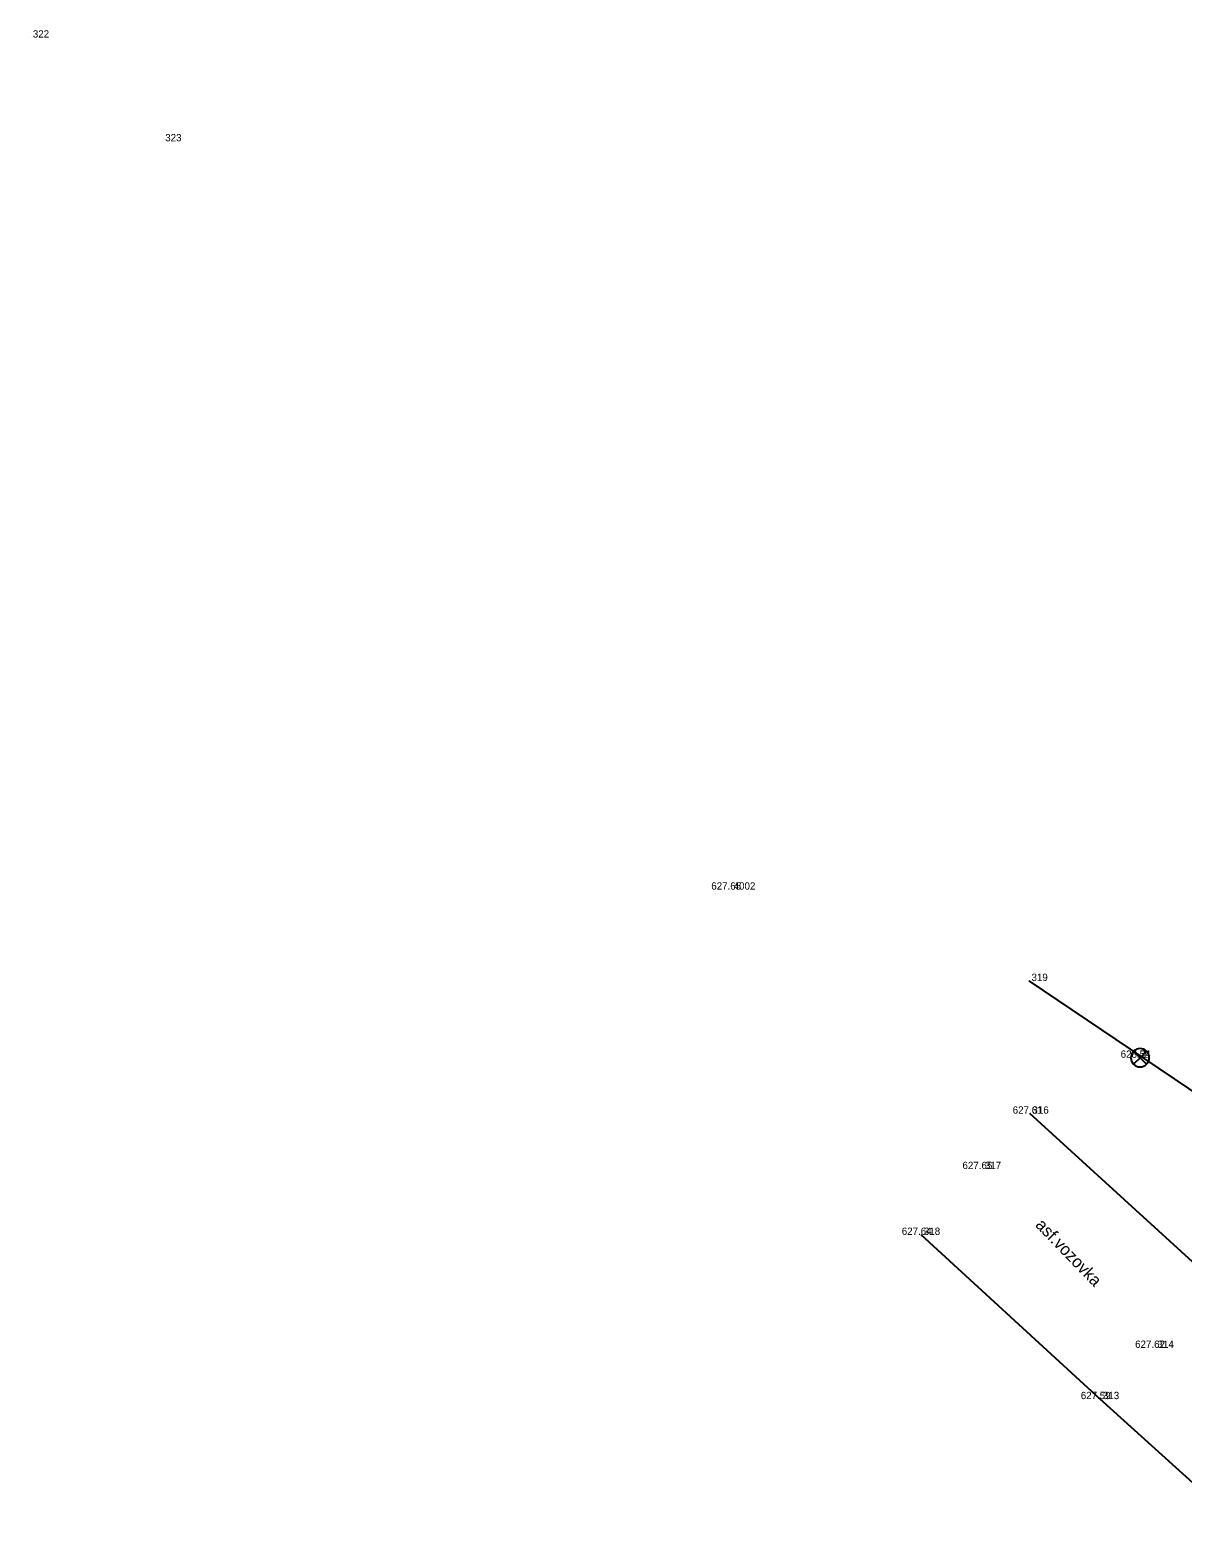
# Model space of a CAD drawing. Extents: x -632073 to -631949, y -1099530 to -1099406.
# Drawn here: x -632073.3 to -632025.8, y -1099467.6 to -1099405.5 of the extents above; entities that cross this region are included whole.
import ezdxf

# ---------------------------------------------------------------- set-up
doc = ezdxf.new("R2010")
doc.units = 0
for name, color, linetype in [('Vrstva 10', 7, 'Continuous'), ('Vrstva 13', 7, 'Continuous'), ('Vrstva 14', 7, 'Continuous'), ('Vrstva 15', 7, 'Continuous'), ('Vrstva 22', 7, 'Continuous'), ('Vrstva 24', 7, 'Continuous'), ('Vrstva 8', 7, 'Continuous')]:
    doc.layers.add(name, color=color, linetype=linetype)

msp = doc.modelspace()

# ---------------------------------------------------------------- linework, layer by layer
at = {"layer": 'Vrstva 10'}
msp.add_line((-632032.18, -1099444.68), (-632022.87, -1099450.95), dxfattribs=at)
at = {"layer": 'Vrstva 13'}
for p, q in [((-632073.29, -1099405.85), (-632073.29, -1099405.85)), ((-632067.84, -1099410.12), (-632067.84, -1099410.12)), ((-632044.44, -1099440.92), (-632044.44, -1099440.92)), ((-632032.18, -1099444.68), (-632032.18, -1099444.68)), ((-632027.6, -1099447.84), (-632027.6, -1099447.84)), ((-632032.14, -1099450.14), (-632032.14, -1099450.14)), ((-632034.1, -1099452.42), (-632034.1, -1099452.42)), ((-632036.61, -1099455.13), (-632036.61, -1099455.13)), ((-632026.99, -1099459.78), (-632026.99, -1099459.78)), ((-632029.24, -1099461.89), (-632029.24, -1099461.89))]:
    msp.add_line(p, q, dxfattribs=at)
at = {"layer": 'Vrstva 24'}
for p, q in [((-632027.865, -1099447.575), (-632027.6, -1099447.84)), ((-632027.335, -1099447.575), (-632027.6, -1099447.84)), ((-632027.335, -1099447.575), (-632027.335, -1099447.575)), ((-632027.6, -1099447.84), (-632027.865, -1099448.105)), ((-632027.6, -1099447.84), (-632027.335, -1099448.105))]:
    msp.add_line(p, q, dxfattribs=at)
for start, end in [(135, 224.96432), (45, 134.96432), (315, 44.96432), (225, 314.96432)]:
    msp.add_arc((-632027.6, -1099447.84), 0.375, start, end, dxfattribs=at)
at = {"layer": 'Vrstva 8'}
for p, q in [((-632024.66, -1099456.95), (-632032.14, -1099450.14)), ((-632029.24, -1099461.89), (-632036.61, -1099455.13)), ((-632022.94, -1099467.6), (-632029.24, -1099461.89))]:
    msp.add_line(p, q, dxfattribs=at)

# ---------------------------------------------------------------- texts
at = {"layer": 'Vrstva 14'}
for s, p in [(' 322', (-632073.29, -1099405.85)), (' 323', (-632067.84, -1099410.12)), (' 4002', (-632044.44, -1099440.92)), (' 319', (-632032.18, -1099444.68)), (' 1', (-632027.6, -1099447.84)), (' 316', (-632032.14, -1099450.14)), (' 317', (-632034.1, -1099452.42)), (' 318', (-632036.61, -1099455.13)), (' 314', (-632026.99, -1099459.78)), (' 313', (-632029.24, -1099461.89))]:
    msp.add_text(s, height=0.3, dxfattribs=at).set_placement(p)
at = {"layer": 'Vrstva 15'}
for s, p in [('627.65 ', (-632045.25, -1099440.92)), ('628.54 ', (-632028.398, -1099447.84)), ('627.61 ', (-632032.843, -1099450.14)), ('627.65 ', (-632034.91, -1099452.42)), ('627.64 ', (-632037.409, -1099455.13)), ('627.62 ', (-632027.803, -1099459.78)), ('627.59 ', (-632030.04, -1099461.89))]:
    msp.add_text(s, height=0.3, dxfattribs=at).set_placement(p)
at = {"layer": 'Vrstva 22'}
msp.add_text('asf.vozovka', height=0.5, rotation=314.01019, dxfattribs=at).set_placement((-632031.939, -1099454.755))

doc.saveas('drawing.dxf')
